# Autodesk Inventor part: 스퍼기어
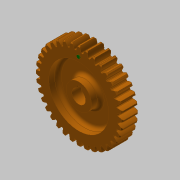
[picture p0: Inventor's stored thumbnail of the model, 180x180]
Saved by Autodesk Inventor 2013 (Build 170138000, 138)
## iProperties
Created: 2019-01
Part Number: 스퍼기어
Material: 알루미늄 6061
Document SubType Name: Modeling
Designer: mduedu
Density: 1 g/cm^3
Author: mduedu
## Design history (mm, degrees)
sketch "스케치1"
  geometry: C1 r 33.5 at (0, 0); C2 r 36 at (0, 0); C3 r 38 at (0, 0); 1 further point
  constraints: 3 centre point, 3 coincident
  dimensions: "d0" = 67 diameter of C1; "d2" = 72 diameter of C2; "d3" = 76 diameter of C3
extrude "돌출1" new body sketch "스케치1" distance "d4" = 14; taper "d5" = 0 deg
sketch "스케치2"
  geometry: L1 (0, 0)-(-38, 0); L2 (0, 0)-(0, 38); L3 (-0.57, 0)-(-0.57, 37.996); L4 (-1.57, 0)-(-1.57, 35.966); L5 (-2.07, 0)-(-2.07, 33.436); A1 r 38 centre (0, 0) between (-38, 0) and (0, 38) reference; A2 r 9.246 centre (7.162, 32.926) between (-0.57, 37.996) and (-2.07, 33.436); A3 r 9.246 centre (-7.162, 32.926) between (2.07, 33.436) and (0.57, 37.996); A4 r 33.5 centre (0, 0) between (2.07, 33.436) and (-2.07, 33.436); A5 r 38 centre (0, 0) between (0.57, 37.996) and (-0.57, 37.996); 2 further points
  constraints: 12 point on circle, 10 end point, 4 centre point, 3 parallel, 3 symmetric about line, 2 coincident, 1 horizontal, 1 perpendicular, 5 other
  dimensions: "d6" = 0.5 distance between parallel lines of L4 L5; "d8" = 1 distance between parallel lines of L3 L4; "d9" = 1.57 distance between parallel lines of L2 L4
extrude "돌출2" join sketch "스케치2" stored distance "d10" = 14; taper "d11" = 0 deg
chamfer "모따기1" distance "d12" = 1; stored, may be unused: second distance "d13" = 2, angle "d14" = 45 deg
fillet "모깎기1" dims "d15" = 0.5
sketch "스케치3"
  geometry: C1 r 11 at (0, 0); 1 further point
  constraints: 1 centre point, 1 coincident
  dimensions: "d19" = 22 diameter of C1
extrude "돌출3" join sketch "스케치3" distance "d20" = 6; taper "d21" = 0 deg
fillet "모깎기2" dims "d22" = 3
sketch "스케치4"
  geometry: C1 r 11 at (0, 0); C2 r 26 at (0, 0); 1 further point
  constraints: 2 centre point, 2 coincident
  dimensions: "d23" = 22 diameter of C1; "d24" = 52 diameter of C2
extrude "돌출4" cut sketch "스케치4" distance "d25" = 8; taper "d26" = 0 deg
fillet "모깎기3" dims "d27" = 3
sketch "스케치5" dims "d28" = 60
  geometry: C1 r 1.5 at (0, 30); 2 further points
  constraints: 2 vertical alignment, 1 centre point, 1 coincident, 2 other
  dimensions: "d29" = 3 diameter of C1
extrude "돌출5" join sketch "스케치5" distance "d30" = 0.5; taper "d31" = 0 deg
sketch "스케치6"
  geometry: L1 (-2, 5.657)-(2, 5.657); L2 (2, 5.657)-(2, 7.8); L3 (2, 7.8)-(-2, 7.8); L4 (-2, 7.8)-(-2, 5.657); A1 r 6 centre (0, 0) between (-2, 5.657) and (2, 5.657); 1 further point
  constraints: 8 end point, 2 parallel, 2 point on circle, 1 centre point, 1 coincident, 1 horizontal, 1 perpendicular
  dimensions: "d32" = 13.8 dimension on A1 L3; "d34" = 4 distance of L2.end L3.end; "d35" = 12 diameter of A1
extrude "돌출6" cut sketch "스케치6" stored distance "d36" = 0.5; taper "d37" = 0 deg
chamfer "모따기2" distance "d38" = 1; stored, may be unused: second distance "d39" = 2, angle "d40" = 45 deg
node "솔리드1"
pattern_circular "원형 패턴1" dims "d17" = 360 deg
